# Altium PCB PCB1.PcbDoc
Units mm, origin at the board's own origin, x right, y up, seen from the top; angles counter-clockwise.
Board outline 0.45 x 30.25 mm, 2 copper layers (Top Layer, Bottom Layer); 14 components, 11 nets, 42 pads, 2 vias.
Unrouted connection lines stored in the file: 24.
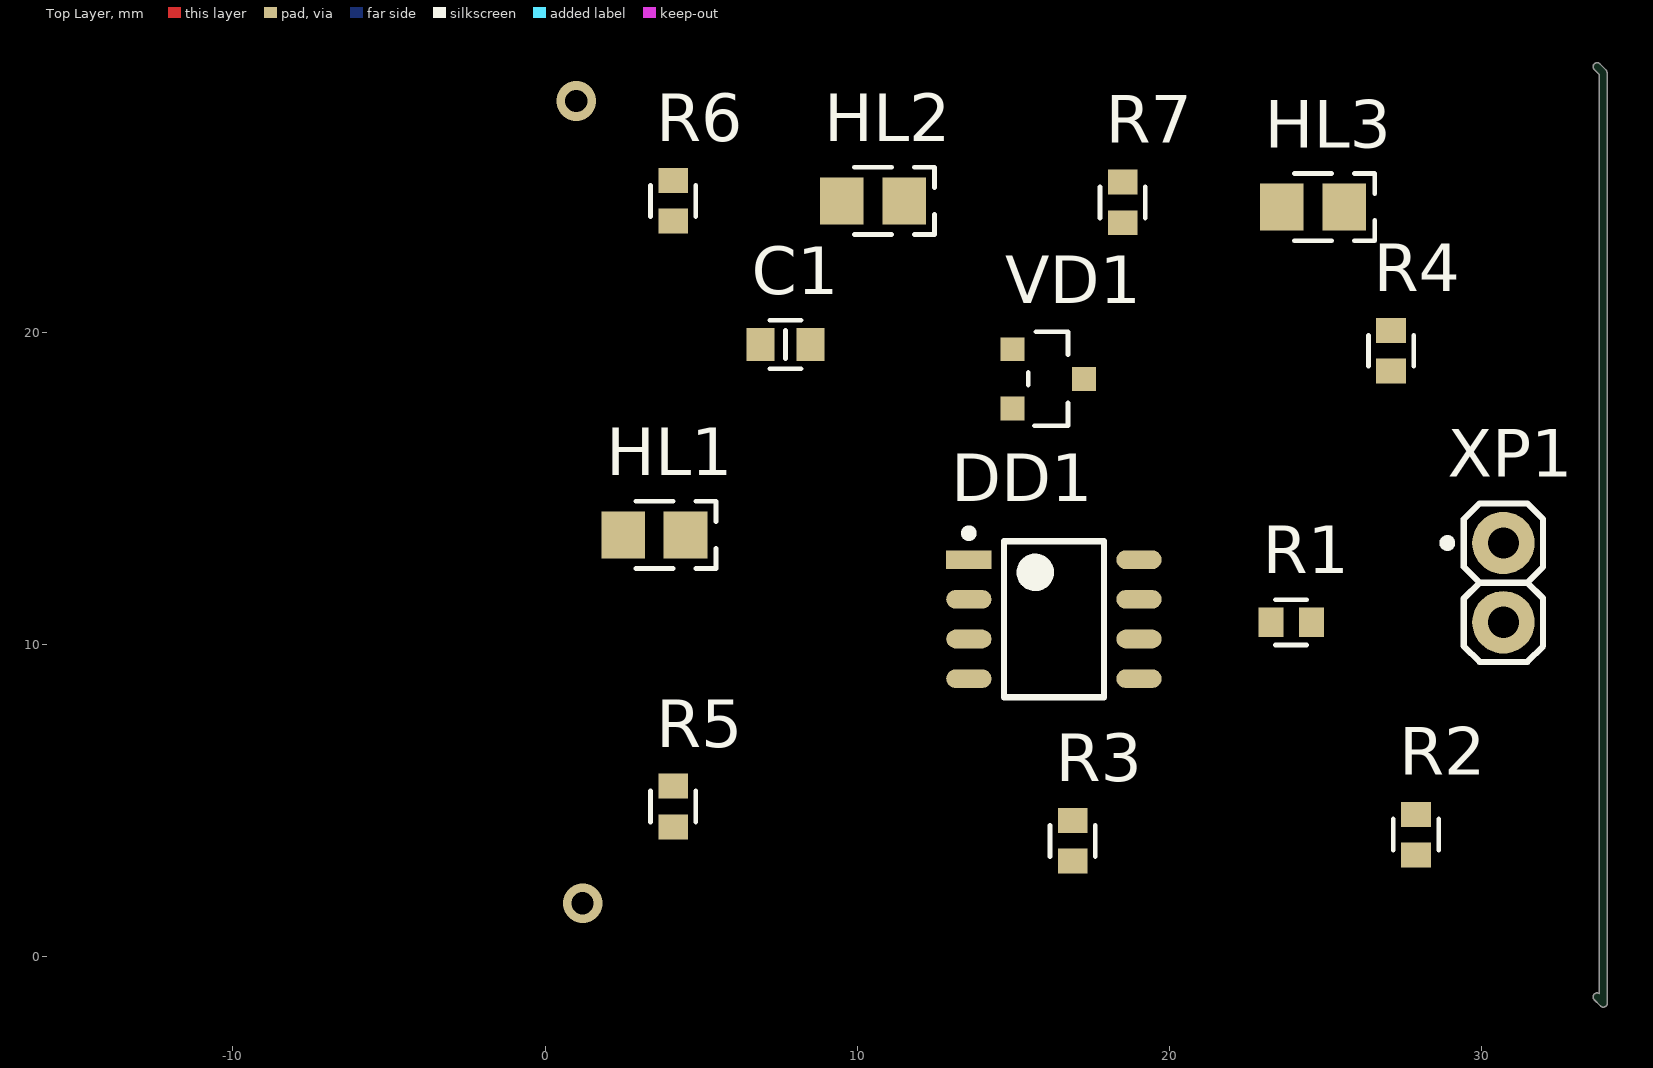
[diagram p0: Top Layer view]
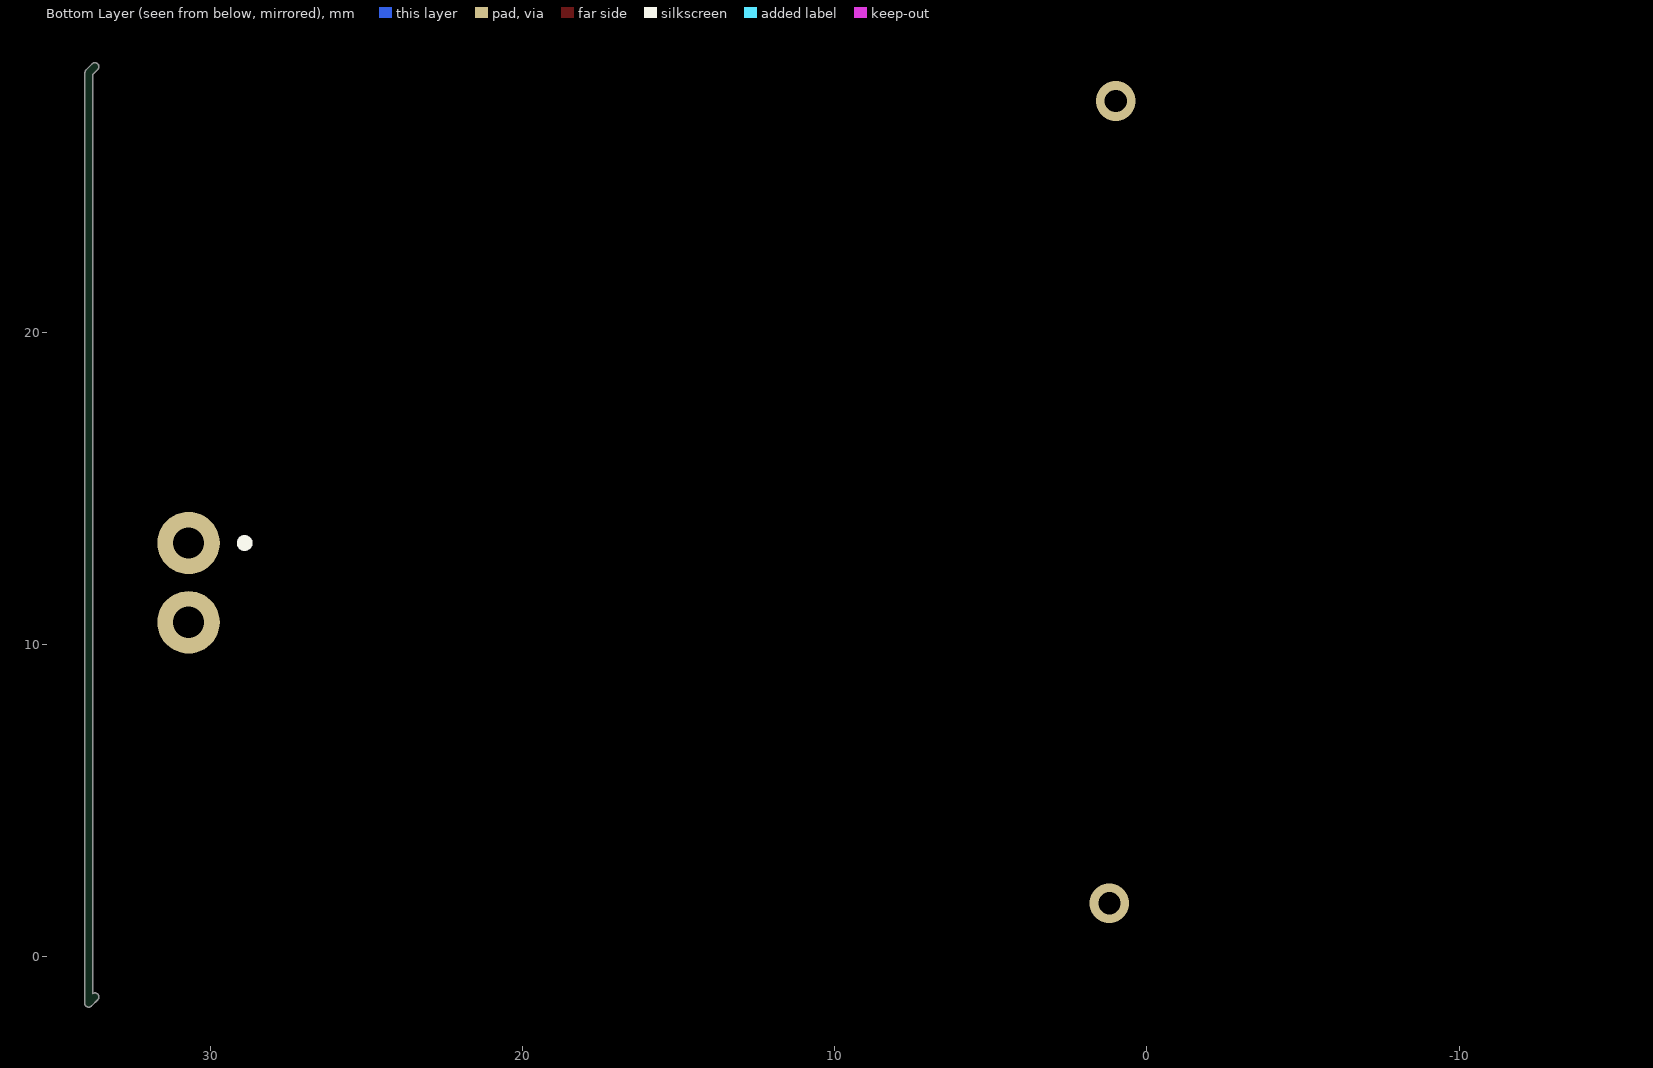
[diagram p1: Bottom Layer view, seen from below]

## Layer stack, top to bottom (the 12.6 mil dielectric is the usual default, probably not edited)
Top Solder: solder mask 0.0102, Solder Resist, Dk 3.5
Top Layer: signal copper 0.0356
Dielectric 1: dielectric 0.32, FR-4, Dk 4.8
Bottom Layer: signal copper 0.0356
Bottom Solder: solder mask 0.0102, Solder Resist, Dk 3.5

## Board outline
33.61,-1.39 cw(c33.7,-1.3) 33.773,-1.195 33.773,28.247 33.61,28.41 cw(c33.7,28.5) 33.79,28.59 33.99,28.39 34.027,28.3 34.027,-1.5 cw(c33.9,-1.5) 33.809,-1.59 33.81,-1.59

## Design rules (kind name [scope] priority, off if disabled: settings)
Clearance [All] p1: gap=0.254 ignorepadtopadclearanceinfootprint=FALSE
PolygonConnect [All] p1: connectstyle=Relief reliefconductorwidth=0.254 reliefentries=4 polygonreliefangle="90 Angle" airgapwidth=0.254
RoutingVias [All] p1: holewidth=0.711 width=1.27 viastyle="Through Hole" minholewidth=0.711 minwidth=1.27 maxholewidth=0.711 maxwidth=1.27
SolderMaskExpansion [All] p1: expansion=0.102 istentingtop=FALSE
Width [All] p1: maxlimit=0.254 minlimit=0.254 preferedwidth=0.254
30 further rules are at their usual default settings.

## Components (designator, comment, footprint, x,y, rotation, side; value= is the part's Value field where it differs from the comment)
C1 "Capacitor" 0603C 7.7,19.6 r0 top value="0,1 мк"
DD1 "LM393" SOIC-8 16.3,10.8 r0 top
HL1 "LED" 0805D 3.5,13.5 r0 top
HL2 "LED" 0805D 10.5,24.2 r0 top
HL3 "LED" 0805D 24.6,24 r0 top
R1 "Resistor" 0603R 23.9,10.7 r0 top value=10
R2 "Resistor" 0603R 27.9,3.9 r90 top value=4,3
R3 "Resistor" 0603R 16.9,3.7 r90 top value="43 к"
R4 "Resistor" 0603R 27.1,19.4 r90 top value=4,3
R5 "Resistor" 0603R 4.1,4.8 r90 top value="10 к"
R6 "Resistor" 0603R 4.1,24.2 r90 top value="10 к"
R7 "Resistor" 0603R 18.5,24.15 r90 top value="10 к"
VD1 "BZX84-B11" SOT23-3 16.1,18.5 r0 top value="11 В"
XP1 "PLS-2" PLS2 30.7,13.24 r0 top

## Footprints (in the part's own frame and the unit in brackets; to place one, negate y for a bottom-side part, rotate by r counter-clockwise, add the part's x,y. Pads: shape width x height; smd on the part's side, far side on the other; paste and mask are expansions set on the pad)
0603C [mm] "Chip Resistor, 2-Leads, Body 1,40x0,80mm, IPC Medium Density"
  rect 0.9x1.05 smd: 1(-0.8,0) 2(0.8,0)
  silkscreen extent -0.5,-0.77 0.5,0.77, body extent -0.85,-0.45 0.85,0.45, height 0.9
0603R [mm] "Chip Resistor, 2-Leads, Body 1.60x0.85mm, IPC Medium Density"
  rect 0.8x0.95 smd: 1(-0.65,0) 2(0.65,0)
  silkscreen extent -0.5,-0.72 0.5,0.72, body extent -0.87,-0.47 0.88,0.48, height 0.9
0805D [mm]
  rect 1.4x1.5 smd: 1(-1,0) 2(1,0)
  silkscreen extent -0.6,-1.07 1.97,1.07, body extent -1.07,-0.7 1.07,0.7, height 0.7
PLS2 [mm]
  round 2 hole 1: 1(0,0) 2(0,-2.54)
  silkscreen extent -1.92,-3.81 1.27,1.27, body extent -1.27,-3.81 1.27,1.27, height 8.44
SOIC-8 [mm] "for operational amplifier"
  rect 1.45x0.6 smd: 1(-2.725,1.905)
  oval 1.45x0.6 smd: 2(-2.725,0.635) 3(-2.725,-0.635) 4(-2.725,-1.905) 5(2.725,-1.905) 6(2.725,-0.635) 7(2.725,0.635) 8(2.725,1.905)
  silkscreen extent -2.85,-2.5 1.6,2.88, body extent -3,-2.5 3,2.5, height 1.75
SOT23-3 [mil]
  rect 30x30 smd: 1(-44.29,37.4) 2(-44.29,-37.6) 3(45.71,-0.1)
  silkscreen extent -25,-59 26,59, body extent -48,-60 50,59, height 41

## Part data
C1: library part Capacitor_0,1u_10_50V_X7R_0603C, "Конденсатор 0603C ёмкостью 0,1 мк 10%, 50 В, X7R", Capacity (nF)=100, Dielectric=X7R, Tolerance=10%, Voltage (V)=50
DD1: "Двойной маломощный компаратор напряжения", Package="SOIC-8 Texas Instruments"
HL1: "Светодиод", Color=Красный
HL2: "Светодиод", Color=Желтый
HL3: "Светодиод", Color=Зеленый
R1: library part Resistor_10_1_0603, "Резистор номиналом 10 Ом 1%", Tolerance=1%
R2 R4: library part Resistor_4.3_1_0603, "Резистор номиналом 4,3 Ом 1%", Tolerance=1%
R3: library part Resistor_43k_1_0603, "Резистор номиналом 43 кОм 1%", Tolerance=1%
R5 R6 R7: library part Resistor_10k_1_0603, "Резистор номиналом 10 кОм 1%", Tolerance=1%
VD1: "Стабилитрон на 11 В, рассеиваемая мощность 0.25 Вт", Current nominal (mA)=5, Power (W)=0.25, Voltage nominal (V)=11
XP1: "Гребенка 2 пина"

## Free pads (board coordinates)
  rect 0.7x1.3 on Mech1: 3(-10.4,16.3) 4(-10.9,0.3) 5(-14.1,26.4) 6(-9.6,22.1) 7(-8.8,23.1) 9(-11.1,0.2)
  round 2 on Mech1: 8(-10.9,0.3)

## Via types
v1: diameter 1.27, hole 0.711, Top Layer to Bottom Layer, 2 vias

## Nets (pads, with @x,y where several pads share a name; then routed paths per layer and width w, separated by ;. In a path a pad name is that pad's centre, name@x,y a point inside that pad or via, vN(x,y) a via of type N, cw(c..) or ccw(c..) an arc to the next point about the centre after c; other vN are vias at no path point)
GND: C1.1 DD1.4 HL3.2 R3.1 VD1.1 VD1.2 XP1.2
NetC1_2: C1.2 DD1.8
NetDD1_1: DD1.1 HL1.2 R6.2
NetDD1_2: DD1.2 DD1.6 R4.1 VD1.3
NetDD1_3: DD1.3 R1.1 R2.2
NetDD1_5: DD1.5 R2.1 R3.2
NetDD1_7: DD1.7 HL2.2 R7.2
NetHL1_1: HL1.1 R5.1
NetHL2_1: HL2.1 R6.1
NetHL3_1: HL3.1 R7.1
NetR1_2: R1.2 R4.2 R5.2 XP1.1
copper on no net:
  other v1: 1.2,1.7 1,27.4

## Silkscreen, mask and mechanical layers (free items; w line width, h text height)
Mechanical 1:
  lines w0.254: 0,0 0,5.2 0,28.5 33.7,28.5 33.9,28.3 33.9,0.1 34,0 0,0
